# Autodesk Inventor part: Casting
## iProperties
Shininess: 77.0
Length Units: 11269
Angle Units: 11279
Time Units: 11290
Mass Units: 11283
Length Display Precision: 3
Angle Display Precision: 2
Created: 2002-02
Part Number: Casting
Document SubType Name: Modeling
Designer: ***
Density: 1 g/cm^3
Density: 0.0
Volumn: 0.0
Area: 0.0
PropertySet Name: Model Information
Control State: 0
Master: False
Checked Out: False
Author: ***
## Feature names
1. Extrusion1
2. Extrusion2
3. Extrusion3
4. Extrusion4
5. Extrusion5
6. Mirror1
7. Extrusion6
